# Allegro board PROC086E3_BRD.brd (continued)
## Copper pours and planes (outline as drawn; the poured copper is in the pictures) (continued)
VCC_CAM_3V3 on BOTTOM: 72.92,176.26 72.91,176.26 72.89,176.27 72.82,176.35 72.81,176.36 72.8,176.38 72.8,178.34 72.8,178.36 72.79,178.38 72.7,178.47 72.68,178.48 72.66,178.48 70.63,178.48 70.61,178.49 70.6,178.5 70.25,178.85 70.23,178.86 70.23,178.88 70.23,181.95 70.23,181.97 70.25,181.99 70.72,182.47 70.74,182.48 70.74,184.62 70.74,184.64 70.75,184.66 70.85,184.75 70.87,184.76 70.89,184.77 71.29,184.77 71.31,184.76 71.33,184.75 71.42,184.66 71.43,184.64 71.44,184.62 71.44,183.27 71.44,183.25 71.45,183.23 71.87,182.81 71.88,182.8 71.88,182.78 71.88,180.09 71.89,180.07 71.9,180.05 72.12,179.83 72.14,179.82 72.16,179.81 74.46,179.81 74.48,179.81 74.5,179.8 74.72,179.58 74.74,179.56 74.74,179.54 74.74,176.41 74.74,176.39 74.72,176.37 74.63,176.27 74.61,176.26 74.59,176.26
VCC_CAM_5V0 on TOP: 62.5,195.19 66.31,195.19 66.31,194.31 62.5,194.31 62.37,194.43 62.37,195.07
VCC_CAM_5V0 on TOP: 71.12,191.45 66.91,191.45 66.81,191.54 66.81,192.78 72.81,192.78 73.28,192.31 73.28,185.61 72.87,185.2 71.81,185.2 71.53,185.48 71.53,191.04
VCC_CAM_5V0 on TOP: 14.67,196.45 18.73,196.45 18.86,196.32 18.86,192.71 18.73,192.58 14.67,192.58 14.54,192.71 14.54,196.32
VCC_CAM_5V0 on L05_PWR1: 13.59,198.48 81.41,198.48 81.79,198.1 81.79,185.15 81.46,184.82 37.34,184.82 36.93,185.23 36.93,187.79 36.53,188.2 13.59,188.2 13.2,188.58 13.2,198.1
VCC_CAM_IO on TOP: 55.13,195.32 59.32,195.32 59.45,195.19 59.45,193.35 59.32,193.23 55.13,193.23 55,193.35 55,195.19
VCC_CAM_IO on L06_PWR2: 33.88,189.82 41.92,189.82 42.13,190.03 42.13,198.07 42.55,198.48 59.82,198.48 60.22,198.08 60.22,181.57 60.66,181.14 74.72,181.14 75.15,180.71 75.15,172.55 74.74,172.14 33.91,172.14 33.63,172.43 33.63,189.56
VCCAD1_5V0 on TOP: 56.13,52.81 60.52,52.81 60.64,52.69 60.64,51.99 60.52,51.86 57.21,51.86 56.77,51.42 56.2,51.42 56.01,51.61 56.01,52.69
VCCAD1_5V0 on L03_SIG1: 41.3,47.73 45.39,47.73 47.73,50.06 57.43,50.06 57.43,53.11 57.01,53.53 42.28,53.53 41.01,52.26 41.01,48.02
VCCAD2_5V0 on TOP: 59.37,104.25 59.88,104.25 59.94,104.19 59.94,103.93 60.13,103.74 64.65,103.74 64.77,103.62 64.77,102.86 64.64,102.73 59.37,102.73 59.25,102.85 59.25,104.12
VCCAD2_5V0 on BOTTOM: 45.11,99.02 60.3,99.02 61.66,100.38 61.66,104.16 61.34,104.48 58.38,104.48 58.25,104.35 58.25,102.54 57.59,101.88 44.53,101.88 44.23,101.58 44.23,99.9
VCCDA1_5V0 on TOP: 60.22,41.34 60.96,41.34 61.15,41.15 61.15,38.15 61.28,38.02 62.09,38.02 62.22,37.89 62.22,36.92 62.12,36.81 60.26,36.81 60.13,36.94 60.13,41.25
VCCDA1_5V0 on L06_PWR2: 42.59,41.26 62.99,41.26 63.25,41 63.25,37.89 62.99,37.64 42.6,37.64 42.28,37.95 42.28,40.95
VCCDA2_5V0 on TOP: 59.94,110.79 64.99,110.79 65.14,110.65 65.14,110.08 64.95,109.9 59.94,109.9 59.77,110.08 59.77,110.62
VCCDA2_5V0 on BOTTOM: 42.54,111.49 60.45,111.49 60.58,111.36 60.58,110.32 60.39,110.12 57.94,110.12 57.69,110.37 49.57,110.37 49.33,110.12 42.29,110.12 42.16,110.24 42.16,111.12
VCCP_IN on TOP: 45.09,75.01 49.35,75.01 49.52,74.85 49.52,73.43 49.35,73.26 45.05,73.26 44.89,73.42 44.89,74.81
VCCP_IN on BOTTOM: 56.19,90.25 56.19,88.4 56.37,88.22 57.62,88.22 57.64,88.25 57.64,90.27 57.5,90.41 56.34,90.41
VCCP_IN on L05_PWR1: 47.75,10.65 47.12,10.02 13.59,10.02 13.21,10.39 13.21,98.6 13.88,99.27 46.85,99.27 46.89,99.23 55.8,99.23 57.17,97.86 57.17,73.04 47.75,63.62
VCCP_OUT on TOP: 36.47,124.44 41.5,124.44 41.76,124.19 41.76,123.12 41.5,122.87 36.47,122.87 36.22,123.12 36.22,124.19
VCCP_OUT on L06_PWR2: 13.13,132.82 41.09,132.82 41.66,132.25 41.66,10.52 41.15,10.02 13.21,10.02 12.65,10.58 12.65,132.34
VDD_3V3_CODEC1 on TOP: 62.1,47.99 64.33,47.99 64.45,47.86 64.45,47.23 64.33,47.1 59.88,47.1 59.66,47.32 59.66,47.68 59.8,47.82 61.93,47.82
VDD_3V3_CODEC1 on L06_PWR2: 42.73,48.31 62.93,48.31 63.18,48.05 63.18,41.89 62.93,41.64 42.63,41.64 42.3,41.97 42.3,47.89
VDD_3V3_CODEC2 on TOP: 67.88,108.44 59.25,108.44 59.06,108.63 59.06,109 59.52,109.46 67.88,109.46 68.01,109.33 68.01,108.57
VDD_3V3_CODEC2 on BOTTOM: 57.78,109.19 57.78,108.34 61.06,108.34 61.06,109.19
VDD_3V3_CODEC2 on L06_PWR2: 42.42,111.81 60.92,111.81 61.15,111.57 61.15,103.68 61.02,103.55 42.42,103.55 42.29,103.68 42.29,111.68
VDDIO_UB926 on TOP: 25.6,171.76 27.58,171.76 27.81,171.99 27.81,173.31 27.38,173.74 27.38,174.84 27.28,174.94 26.82,174.94 26.72,174.83 26.72,173.92 26.42,173.62 26.11,173.62 25.58,173.08 25.58,171.79
VDDIO_UB926 on L06_PWR2: 19.82,189.83 32.83,189.83 33.02,189.64 33.02,173.21 32.77,172.96 19.94,172.96 19.56,173.34 19.56,189.57
(no net) on TOP: 1.02,10.84 1.02,22.53 6.03,22.53 6.29,22.78 6.29,29.83 6.03,30.08 1.02,30.08 1.02,38.91 5.91,38.91 6.16,39.16 6.16,46.08 5.91,46.34 1.02,46.34 1.02,55.35 5.91,55.35 6.16,55.61 6.16,62.34 5.91,62.59 1.02,62.59 1.02,71.61 5.97,71.61 6.22,71.86 6.22,78.72 5.97,78.98 1.02,78.98 1.02,87.87 5.91,87.87 6.16,88.12 6.16,95.11 5.91,95.36 1.02,95.36 1.02,104.25 6.03,104.25 6.29,104.5 6.29,111.43 6.03,111.68 1.02,111.68 1.02,120.63 5.97,120.63 6.22,120.89 6.22,127.74 5.97,128 1.02,128 1.02,198.17 1.33,198.48 81.43,198.48 81.81,198.1 81.81,190.74 82.09,190.46 86.93,190.46 87.19,190.71 87.19,192.12 87.5,192.43 97.17,192.43 97.47,192.13 97.47,190.8 97.82,190.46 101.37,190.46 101.6,190.23 101.6,10.52 101.09,10.02 1.84,10.02 ; 159 cut-outs
(no net) on BOTTOM: 1.84,10.02 1.02,10.84 1.02,22.53 6.03,22.53 6.29,22.78 6.29,29.83 6.03,30.08 1.02,30.08 1.02,38.91 5.91,38.91 6.16,39.16 6.16,46.08 5.91,46.34 1.02,46.34 1.02,55.35 5.91,55.35 6.16,55.61 6.16,62.34 5.91,62.59 1.02,62.59 1.02,71.61 5.97,71.61 6.22,71.86 6.22,78.72 5.97,78.98 1.02,78.98 1.02,87.87 5.91,87.87 6.16,88.12 6.16,95.11 5.91,95.36 1.02,95.36 1.02,104.25 6.03,104.25 6.29,104.5 6.29,111.43 6.03,111.68 1.02,111.68 1.02,120.63 5.97,120.63 6.22,120.89 6.22,127.74 5.97,128 1.02,128 1.02,198.17 1.33,198.48 81.43,198.48 81.81,198.1 81.81,190.74 82.09,190.46 87.43,190.46 88.77,189.12 101.6,189.12 101.6,10.52 101.09,10.02 ; 151 cut-outs
(no net) on L03_SIG1: 1.02,10.02 1.02,198.48 101.67,198.48 101.67,10.02 ; 61 cut-outs
EXP_3V3 on TOP: 90.68,46.27 93.6,46.27 93.73,46.15 93.73,44.75 93.6,44.62 90.68,44.62 90.55,44.75 90.55,46.15
EXP_DC_3V3 on L06_PWR2: 81.92,54.96 93.7,54.96 93.94,54.72 93.94,51.7 93.73,51.48 81.85,51.48 81.53,51.81 81.53,54.57
SHLD_GND_HDMI1 on TOP, L02_GND1, L04_GND2, L07_GND3, L08_SIG2, L09_GND4: 82.45,191.3 82.45,198.1 82.83,198.48 100.76,198.48 101.6,197.65 101.6,191.12 101.42,190.94 98.34,190.94 97.85,191.43 97.85,192.51 97.54,192.83 87.12,192.83 86.8,192.51 86.8,191.14 86.6,190.94 82.8,190.94
SHLD_GND_HDMI1 on BOTTOM: 98.42,188.73 98.3,188.86 98.3,190.98 97.85,191.43 97.85,192.51 97.54,192.83 87.12,192.83 86.8,192.51 86.8,191.14 86.6,190.94 82.8,190.94 82.45,191.3 82.45,198.1 82.83,198.48 100.76,198.48 101.6,197.65 101.6,188.91 101.42,188.73
V_DVDD on L05_PWR1: 78.87,169.15 97.16,169.15 97.28,169.02 97.28,155.88 97.16,155.75 78.87,155.75 78.74,155.88 78.74,169.02
V_TVDD on L05_PWR1: 82.68,171.94 93.03,171.94 93.15,171.81 93.15,169.65 93.03,169.53 82.68,169.53 82.55,169.65 82.55,171.81
VCOMAD1 on L08_SIG2: 17.88,75.3 32.54,75.3 41.89,65.95 41.89,48.68 39.87,46.66 19.02,46.66 15.45,50.23 15.45,72.87
VCOMAD1_CODEC on TOP: 45.9,48.27 45.9,49.86 45.41,50.36 43.01,50.36 42.93,50.44 42.93,51.73 43.02,51.82 45.9,51.82 45.9,51.83 46.75,51.83 47.57,51.01 47.57,48.45 47.4,48.27
VCOMAD1_CODEC on BOTTOM: 42.84,51.98 42.84,50.19 44.58,50.19 44.58,51.98
VCOMAD2 on L03_SIG1: 57.83,100.06 13.07,100.06 12.64,99.62 12.64,69.39 12.89,69.13 58.36,69.13 58.69,69.46 58.69,88.7 57.83,89.55
VCOMAD2_CODEC on TOP: 58.8,103.51 58.8,98.9 59.13,98.57 59.13,97.13 59,97 58.63,97 58.62,97.01 56.95,97.01 56.74,97.21 56.74,103.31 56.97,103.54 58.78,103.54
VCOMAD2_CODEC on BOTTOM: 57.69,96.64 59.28,96.64 59.28,98.66 59.07,98.87 57.29,98.87 57.13,98.7 57.13,97.2 57.13,97.2
VSYS_IO_3V3 on TOP: 90.37,75.62 90.37,74.66 90.58,74.46 93.4,74.46 93.6,74.25 95.73,74.25 95.94,74.46 95.94,75.8 95.71,76.03 93.75,76.03 93.52,75.8 90.55,75.8

Small or netless copper shapes (teardrops, artwork), in the pictures only: 5 on BOTTOM

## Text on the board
Ref Des/Assembly Bottom: BOTTOM ASSEMBLY  REV.E3 | PR0C086 J7X INFOTAINMENT EXP BRD
Ref Des/Silkscreen Bottom: FPD-DISPLAY | DIR:OPTIC IN | DIR:COAX IN | DGND | DIR_EMPH | [R] | CODEC A | 3/4 | 1/2 | MIC | [L] | CAMERA-OMNI | CAMERA-LI | DIT | EXP_P1 | HDMI | EXP_P2 | FPD-AUDIO | COAX | OPTIC | DIR:IN SEL SW | 5/6 | 7/8 | DIR_ERROR | LINE OUT | CODEC B | LINE IN 5/6 | DIR_AUDIO# | VCC_5V0 | EXP_P3 | VCC_1V8 | VCC_12V | VCC_3V3 | OPN# | ASSY | SL# | J7EXPE01EVM | J7X INFOTAINMENT EXP BRD | PCB# PROC086E3
User.Comments: CR_T3_1 | CR_T3_2 | CR_T7_1 | CR_T7_2 | CR_1_2 | CR_T2_3 | CR_T2_1 | CR_T2_2 | BOARD NAME: | PR0C086 J7X INFOTAINMENT EXP BRD | REV: E3 | DATE: 23/08/2019 | DESCRIPTION: | SHEET | OF | 21 | PROC086 | SCALE: 1 | TEXAS INSTRUMENTS
Ref Des/Assembly Top: PR0C086 J7X INFOTAINMENT EXP BRD | TOP ASSEMBLY  REV.E3
Ref Des/Silkscreen Top: FOR EVALUATION ONLY; | NOT FCC APPROVED FOR RESALE | EXP_CONN1 | EXP_CONN2
PAGE_OUTLINE: LAYOUT BY | REVIEWED BY | APPROVED BY | SIGNATURES | AMB | UD | USK | DATE | 230819 | SIZE | SCALE: | D | NONE | SHEET 1 OF 21 | PROC086 | Rev | E3 | TEXAS INSTRUMENTS | J7X INFOTAINMENT EXP BRD
User.5: 12. | 13. | 14. | 11. | MINIMUM TRACEWIDTH AND SPACEING:0.0035"/0.0061" | PCB SHALL BE Pb FREE & RoHS COMPLAINT. | ALL UNCONNECTED VIA'S SHALL BE SUPPRESSED IN ALL INTERNAL LAYERS. | FINISHED BOARD THICKNESS :0.079"+/-10%
User.10: R350 | R337 | R370 | R367 | C469 | C465 | R365 | R359 | R360 | R356 | C460 | C452 | C453 | C448 | R407 | R408 | R409 | R410 | R385 | C487 | C490 | R386 | C488 | R366 | C468 | R357 | R358 | C466 | C461 | R349 | C455 | R348 | C456 | C523 | C520 | R430 | R431 | R432 | R426 | C519 | R428 | R427 | R424 | R425 | R422 | R423 | C502 | R429 | C508 | C512 | C516 | C522 | C500 | R414 | C501 | R415 | R420 | R413 | R392 | R411 | C497 | R397 | R441 | C496 | C467 | C483 | C495 | R396 | C463 | R436 | C470 | R345 | C515 | R346 | C454 | R347 | C426 | C446 | R321 | R322 | C444 | R330 | C442 | C440 | R312 | C427 | C429 | R318 | C437 | C438 | R323 | C435 | C436 | R313 | C434 | R317 | C433 | C430 | C425 | R310 | R311 | C411 | C424 | C422 | C423 | C389 | R308 | C390 | R309 | C415 | C417 | C410 | C414 | C407 | C408 | C409 | C412 | C525 | C413 | C404 | C403 | L112 | C210 | C381 | C382 | C375 | C384 | C383 | C340 | R299 | R300 | C385 | R303 | R187 | R307 | C388 | R288 | R306 | R184 | C374 | R283 | R301 | R302 | R284 | R474 | C362 | R472 | C377 | R286 | R287 | R293 | R294 | R295 | R296 | R285 | R289 | R290 | R291 | R292 | R475 | R473 | C361 | R280 | R281 | R278 | R279 | R277 | R276 | C336 | C372 | C342 | C345 | C339 | R275 | R274 | C369 | C352 | L106 | R233 | R234 | C315 | C316 | R248 | R249 | R251 | R250 | C312 | C319 | C321 | C320 | C318 | C355 | C347 | R245 | C298 | C297 | C364 | L105 | FL1 | R260 | R262 | R264 | R266 | R258 | R256 | C284 | C285 | C286 | C287 | C288 | C290 | C291 | C292 | C293 | C294 | C303 | C304 | C308 | C305 | C306 | C307 | C300 | C302 | C301 | C299 | R257 | R267 | R259 | R261 | R263 | R265 | R443 | L114 | R442 | R447 | C521 | R418 | C499 | C491 | C518 | L113 | R406 | C507 | R382 | R444 | C492 | R383 | R377 | C506 | R387 | R421 | R378 | C494 | R372 | R445 | R373 | C504 | R389 | C472 | C473 | C458 | C464 | C503 | R393 | R343 | R419 | C459 | R335 | R417 | R344 | R327 | R390 | R336 | C511 | R380 | R394 | R328 | R391 | R416 | R375 | C489 | R412 | R381 | C493 | C477 | C485 | R395 | C484 | R376 | C482 | C476 | R388 | R371 | R384 | C478 | C481 | C471 | C486 | R379 | R368 | C462 | C514 | C513 | R374 | C479 | R362 | R369 | C457 | R352 | R353 | R342 | R341 | C449 | R339 | R333 | R334 | R332 | C480 | C443 | C441 | C475 | R340 | R361 | R326 | C474 | R324 | C447 | R364 | R351 | R325 | R363 | R329 | R355 | R338 | R354 | R331 | C451 | C450 | 1 | 2 | C431 | C420 | C428 | R315 | R316 | C387 | R314 | C401 | C416 | C418 | C419 | C394 | C386 | C391 | C402 | C400 | R297 | C380 | R305 | C371 | R304 | L111 | C378 | C367 | C528 | R182 | C405 | C406 | C526 | C399 | R282 | C398 | C356 | C379 | C373 | C396 | C395 | C344 | C393 | C392 | R298 | C335 | C351 | C338 | C370 | C331 | C343 | C330 | C334 | C325 | C332 | L110 | L109 | C326 | C360 | R320 | L108 | C322 | C359 | C376 | C328 | L107 | C327 | R319 | C358 | C324 | C329 | C357 | C323 | C348 | R241 | C333 | C341 | C363 | C354 | C346 | C337 | R255 | R252 | R253 | R254 | C314 | C311 | C310 | R243 | R247 | C309 | R231 | R232 | R244 | R242 | R246 | C317 | R230 | R229 | R228 | R235 | R236 | R237 | R238 | R239 | R240 | C283 | C353 | R223 | C278 | C313 | R268 | R269 | R270 | R271 | R272 | R273 | C296 | C368 | C295 | C289 | R224 | R226 | C282 | C279 | C280 | C281 | R219 | R221 | R225 | R227 | C276 | C277 | R220 | R222 | C274 | C275 | C273 | FB2 | 80 | 42 | 120 | 79 | 119 | 41 | SD Card | P4 | EXP_P1 | EXP_P3 | EXP_P2 | TURNING CONCEPT | AUSTIN,TEXAS 78756 | INTO REALITY | 4410 SHOALWOOD | (512)260-5778 | SPECTRUM DIGITAL | DATE: | BSLK | 5-28-13 | 517181 REV B | BREAK OFF TAB
User.11: CARD EJECTED | CARD LOCK | CARD OVER STROCK | D | C | B | A | BASY CP CARD REV E3
User.13: PRIMARY-PASTEMASK | 16
User.14: SECONDARY-PASTEMASK | 17
User.15: SECONDARY-SOLDERMASK | 14
User.16: SECONDARY-SILKSCREEN | 15
User.17: SECONDARY-SIDE-SIG | 13
User.27: GROUND-PLANE-04 | 12
User.29: GROUND-PLANE-03 | 10
User.30: INNER-SIGNAL-02 | 11
User.31: POWER-PLANE-01 | 08
User.32: POWER-PLANE-02 | 09
User.33: INNER-SIGNAL-01 | 06
User.34: GROUND-PLANE-02 | 07
User.35: PRIMARY-SIDE-SIG | 04
User.36: GROUND-PLANE-01 | 05
User.37: PRIMARY-SILKSCREEN | 02
User.38: PRIMARY-SOLDERMASK | 03
User.39: 02 | 03 | 04 | L3/L8 | L1/L10 | 7 | 4.2 | 3.5 | - | 8 | 100 | 50 | L2/L4,L7/L9 | L2/L9
User.40: 0.005 | 0.0037 | 1oz. | L08 | L09 | POWER-PLANE-2 | GROUND-PLANE-2 | INNER-SIGNAL-2 | GROUND-PLANE-4
User.43: FIGURE | SIZE | 8.0 | 30.0 | 34.0 | 40.0 | 46.0 | 52.0 | 60.0 | 66.0 | 78.0 | 32.0 | 108.0 | 126.0 | 158.0x78.0 | DRILL CHART: TOP to BOTTOM | ALL UNITS ARE IN MILS | TOLERANCE | +3.0/-3.0 | PLATED | NON-PLATED | QTY | 1815 | 2 | 5 | 58 | 4 | 42 | 10 | 18 | 14
User.44: 3 - Board assembly must comply with workmanship standards IPC-A-610 Class 2, unless otherwise specified. | 1 - All MSL components should be baked as per JEDEC standard. | 2 - PCB should be baked at 120 degree for 8 hours. | 4 - These assemblies are ESD sensitive, ESD precautions shall be observed. | 5 - These assemblies must be clean and free from flux and all contaminants. Use of no clean flux is not acceptable. | 6 - Provide serial numbers to the assembled boards for identification. | ASSEMBLY NOTES:- | 7 - The assembled board are wrapped in ESD Covers(individual) and packed securely before shipment. | PROC086 E2 ASSEMBLY TOP
User.45: PROC086 E2 ASSEMBLY BOTTOM | 7 - The assembled board are wrapped in ESD Covers(individual) and packed securely before shipment. | ASSEMBLY NOTES:- | 5 - These assemblies must be clean and free from flux and all contaminants. Use of no clean flux is not acceptable. | 6 - Provide serial numbers to the assembled boards for identification. | 2 - PCB should be baked at 120 degree for 8 hours. | 4 - These assemblies are ESD sensitive, ESD precautions shall be observed. | 1 - All MSL components should be baked as per JEDEC standard. | 3 - Board assembly must comply with workmanship standards IPC-A-610 Class 2, unless otherwise specified.
